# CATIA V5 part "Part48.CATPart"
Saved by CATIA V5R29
Part number: spur gear_iso_ISO - Spur gear 0.5M 32T 20PA 6FW ---S32A75H50L3.0N
Revision: ANY
Definition: UNKNOWN
Nomenclature: spur gear_iso_ISO - Spur gear 0.5M 32T 20PA 6FW ---S32A75H50L3.0N
Source: Unknown
Bounding box of the stored display mesh (mm): x 0 to 6, y -8.472 to 8.472, z -8.472 to 8.472
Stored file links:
  C:\Users\Administrator\Desktop\프로젝트\Gripper\Part48.CATPart
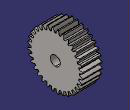
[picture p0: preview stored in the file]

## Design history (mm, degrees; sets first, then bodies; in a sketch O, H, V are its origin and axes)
Body1 "Bore" (main body)
  Solid1: solid without history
